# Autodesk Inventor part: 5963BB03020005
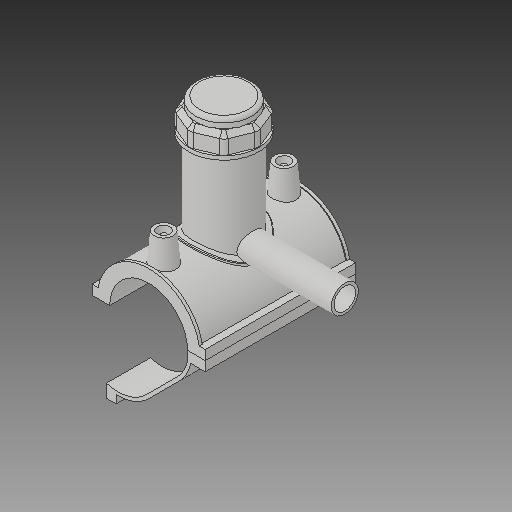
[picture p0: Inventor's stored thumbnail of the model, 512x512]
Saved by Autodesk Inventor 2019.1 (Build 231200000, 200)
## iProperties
Created: 2017-07
Part Number: 5963BB03020005
Material: Generic
Description: PLASSON TAPPING SADDLE 2''IPS x 1 1/2''IPS
Document SubType Name: Modeling
Designer: KIM
Mass: 1712.7 g
Surface Area: 2671.49 cm^2
Volume: 1712.7 cm^3
Density: 1 g/cm^3
Appearance: Default
Author: KIM
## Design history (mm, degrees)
derived "5963B.ipt"
feature "Solid1::5963B.ipt"
feature "Solid2::5963B.ipt"
feature "Solid4::5963B.ipt"
feature "Solid5::5963B.ipt"
tag "TaggingFeature1"
body "Solid1"
body "Solid2"
other parameters: "d0" = 61.1, "d2" = 88.9, "d3" = 15.275, "d4" = 118.11, "d5" = 0, "d6" = 0.1, "d8" = 0, "d19" = 6, "d20" = 6, "d21" = 70.866, "d23" = 0, "d24" = 35.433, "d26" = 0, "d29" = 3, "d30" = 20.36667, "d31" = 6, "d32" = 0, "d33" = 0, "d34" = 0.6, "d40" = 41.3036, "d41" = 54.99, "d43" = 0, "d45" = 0, "d47" = 110.581, "d70" = 15, "d72" = 0, "d73" = 6, "d75" = 5, "d76" = 0, "d77" = 3.055, "d78" = 60.55, "d79" = 15, "d80" = 47.244, "d82" = 5 deg, "d84" = 4, "d85" = 14, "d86" = 0, "d87" = 3, "d88" = 0, "d89" = 1, "d90" = 1, "d91" = 94.488, "d92" = 0, "d93" = 0.5, "d94" = 32.15789, "d96" = 81.0186, "d97" = 2.3622, "d98" = 0, "d102" = 0.611, "d120" = 140 deg, "d121" = 24.228, "d122" = 20 deg, "d123" = 158.86, "d124" = 47.658, "d126" = 0, "d143" = 62.933, "d145" = 14.1, "d149" = 0.9165, "d150" = 15.51, "d153" = 118.11, "d154" = 0, "d156" = 39.715, "d157" = 160 deg, "d159" = 3.666, "d161" = 0.9165, "d162" = 70.866, "d163" = 0, "d164" = 30.55, "d167" = 6.11, "d168" = 38.74634, "d170" = 3.2805, "d172" = 0, "d173" = 1, "d175" = 30.55, "d176" = 20 deg, "d177" = 4.277, "d178" = 18.33, "d180" = 0, "d183" = 7.332, "d184" = 3.4216, "d185" = 38.38575, "d186" = 38.38575, "d187" = 39.715, "d188" = 5.499, "d189" = 4.277, "d190" = 0, "d191" = 59.5725, "d193" = 6.1236, "d194" = 4.13385, "d195" = 90 deg, "d197" = 0, "d199" = 0, "d200" = 9.165, "d202" = 0, "d203" = 98.044, "d204" = 52.2405, "d205" = 38.493, "d206" = 46.7415, "d207" = 73.533, "d208" = 76.47432, "d209" = 91.18092, "d210" = 47.2914, "d211" = 54.99, "d212" = 43.992, "d213" = -2.9106, "d216" = 0, "d217" = 6.11, "d218" = 3.055, "d219" = 0.611, "d222" = 61.1, "d224" = 0, "d230" = 3.666, "d233" = 6, "d236" = 44.45, "d237" = 35.433, "d238" = 6.02433, "d240" = 35.433, "d241" = 35.433, "d242" = 35.433, "d243" = 6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
